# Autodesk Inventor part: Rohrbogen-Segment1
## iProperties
Created: 2006-10
Part Number: Rohrbogen-Segment1
Cost Center: 0,5 kg
Material: 1.4301 (X5CrNi18 10)
Document SubType Name: Sheet Metal
Designer: grote
Authority: 62965,5 mm^3
Manufacturer: Standard
Standards Organization: Custom
Objekthöhe: 10,000 mm
SaveDate: 2006-10-11
SaveTime: 08:21
FileName: Rohrbogen-Segment1
TotalMass: 0,5 kg
TotalVolume: 62965,5 mm^3
SM_Thickness: 10 mm
SM_Style: NIRO-V80(t =4-10 mm)
SM_Extents: 94,851 mm x 102,973 mm
SM_Square: 9767 mm²
SM_Extents_Width: 94,851 mm
SM_Extents_Length: 102,973 mm
Author: grote
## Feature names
1. Trennen1
2. Abgeleiteter Körper1 [Tagging]
3. ExtrusionAbwicklung1
